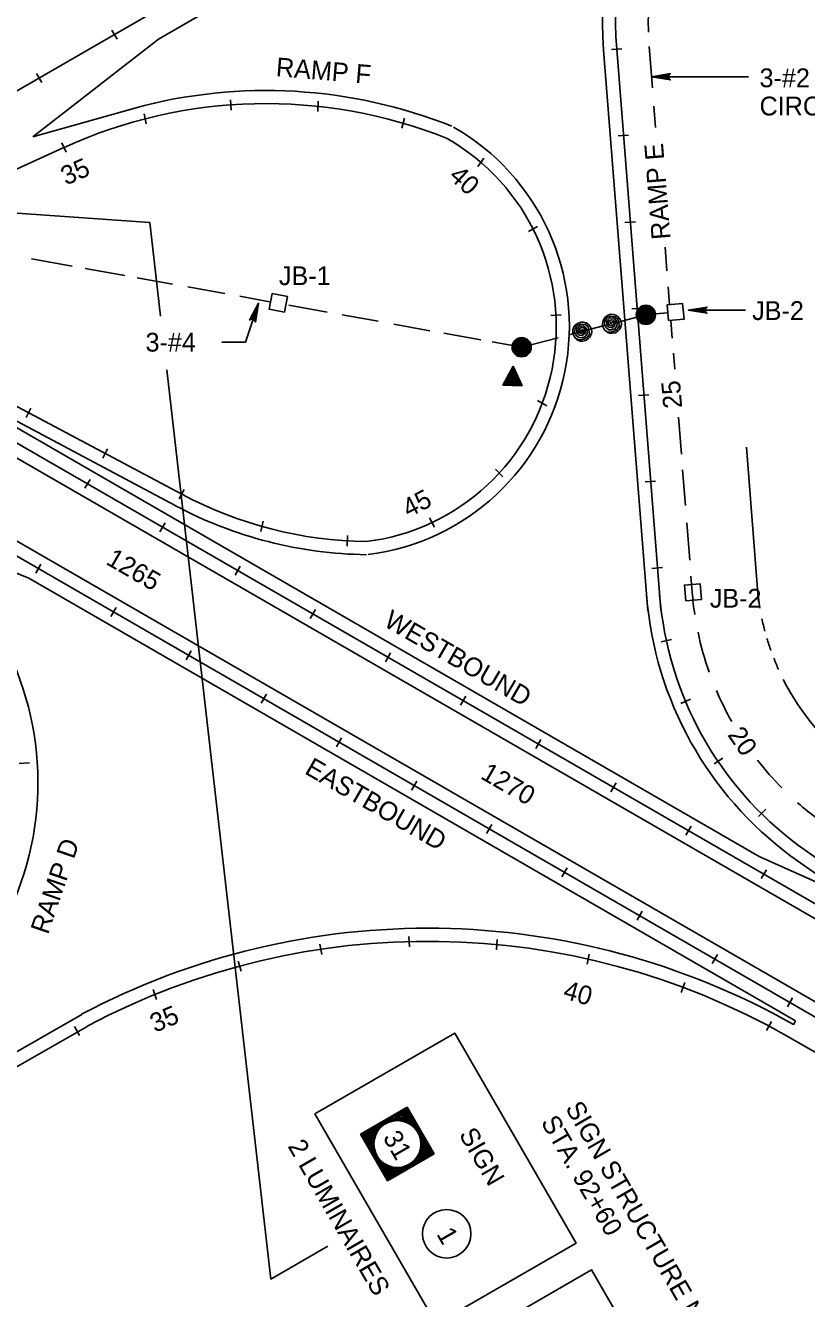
# Model space of a CAD drawing. Extents: x 36 to 2622, y -5330 to 219.
# Drawn here: x 469.4 to 593.7, y -5134.2 to -4931.5 of the extents above; entities that cross this region are included whole.
import ezdxf

# ---------------------------------------------------------------- set-up
doc = ezdxf.new("R2010")
doc.units = 0
doc.layers.add('2', color=7, linetype='Continuous')
doc.layers.add('3', color=7, linetype='Continuous')

# ---------------------------------------------------------------- blocks, each defined once
blk = doc.blocks.new('RARROW')
at = {"layer": '3'}
blk.add_lwpolyline([(-2.2695, 0.285), (-2.184875, 0.12075), (0, 0), (-2.2695, 0.285), (-2.38575, 0.384625), (0, 0), (-2.183125, -0.108), (-2.262875, -0.2705), (0, 0), (-2.38575, -0.379125), (-2.262875, -0.2705)], dxfattribs=at)

msp = doc.modelspace()

# ---------------------------------------------------------------- linework, layer by layer
at = {"layer": '2'}
for p, q in [((569.35, -4888.23), (490.57, -4933.71)), ((280.19, -5050.39), (555.32, -4891.55)), ((483.96, -4933.71), (483.13, -4932.27)), ((490.57, -4933.71), (470.58, -4949.25)), ((568.45, -5024.74), (561.42, -4935.47)), ((562.67, -4935.37), (564.33, -4935.24)), ((563.5, -4935.31), (570.52, -5024.58)), ((568.68, -4934.9), (569.2, -4941.45)), ((472, -4940.61), (471.17, -4939.18)), ((584.5, -4939.7), (569.06, -4939.7)), ((502.01, -4943.36), (502.12, -4945.02)), ((516, -4943.6), (515.95, -4945.26)), ((486.78, -4944.7), (470.58, -4949.25)), ((488.26, -4945.6), (488.6, -4947.22)), ((569.7, -4947.8), (569.43, -4944.37)), ((529.71, -4946.32), (529.29, -4947.92)), ((563.75, -4949.14), (565.4, -4949.02)), ((475.52, -4950.97), (441.69, -4966.41)), ((475.87, -4951.73), (475.18, -4950.22)), ((542.36, -4952.66), (541.39, -4954.01)), ((489.19, -4962.94), (465.78, -4961.29)), ((490.89, -4977.83), (489.19, -4962.94)), ((550.92, -4963.57), (549.45, -4964.35)), ((564.82, -4962.92), (566.47, -4962.79)), ((571.2, -4966.87), (571.5, -4970.62)), ((476.84, -4969.86), (470.33, -4968.69)), ((485.23, -4971.37), (478.87, -4970.23)), ((492.79, -4972.74), (487.19, -4971.73)), ((494.27, -5006.17), (433.76, -4974)), ((501.14, -4974.24), (495.26, -4973.18)), ((571.92, -4976.01), (571.7, -4973.16)), ((508.24, -4975.53), (503.5, -4974.67)), ((504.42, -4981.97), (506.49, -4975.77)), ((517.39, -4977.18), (511.33, -4976.09)), ((699.62, -5134.16), (428.19, -4977.45)), ((525.54, -4978.65), (519.8, -4977.61)), ((554.65, -4977.6), (553, -4977.72)), ((568.15, -4977.62), (563.3, -4978.89)), ((565.89, -4976.68), (567.55, -4976.56)), ((571.62, -4977.29), (568.3, -4977.58)), ((583.99, -4976.87), (574.9, -4976.87)), ((700.67, -5132.35), (434.98, -4978.96)), ((533.78, -4980.14), (528.02, -4979.1)), ((561.55, -4979.34), (556.11, -4980.76)), ((572.12, -4978.5), (572.34, -4981.35)), ((500.62, -4981.97), (504.42, -4981.97)), ((541.87, -4981.6), (536, -4980.54)), ((548.38, -4982.77), (543.69, -4981.92)), ((548.38, -4982.77), (554.16, -4981.27)), ((693.9, -5144.07), (416.96, -4984.17)), ((572.73, -4986.29), (572.53, -4983.7)), ((692.86, -5145.87), (414.78, -4985.32)), ((508.44, -5131.18), (491.87, -4986.4)), ((545.38, -4988.82), (547, -4985.8)), ((545.57, -4988.72), (546.99, -4986.04)), ((545.74, -4988.61), (546.98, -4986.29)), ((546.98, -4986.29), (548.1, -4988.67)), ((546.99, -4986.04), (548.27, -4988.79)), ((547, -4985.8), (548.45, -4988.91)), ((545.93, -4988.51), (546.98, -4986.53)), ((546.1, -4988.4), (546.97, -4986.78)), ((547.75, -4988.45), (546.1, -4988.4)), ((546.28, -4988.3), (546.97, -4987.02)), ((547.58, -4988.33), (546.28, -4988.3)), ((546.46, -4988.19), (546.96, -4987.26)), ((547.41, -4988.22), (546.46, -4988.19)), ((546.64, -4988.09), (546.95, -4987.51)), ((547.23, -4988.11), (546.64, -4988.09)), ((546.82, -4987.98), (546.95, -4987.75)), ((547.06, -4987.99), (546.82, -4987.98)), ((546.95, -4987.51), (547.23, -4988.11)), ((546.95, -4987.75), (547.06, -4987.99)), ((546.96, -4987.26), (547.41, -4988.22)), ((546.97, -4986.78), (547.75, -4988.45)), ((546.97, -4987.02), (547.58, -4988.33)), ((546.98, -4986.53), (547.93, -4988.56)), ((493.3, -5008.01), (459.78, -4990.19)), ((548.45, -4988.91), (545.38, -4988.82)), ((548.27, -4988.79), (545.57, -4988.72)), ((548.1, -4988.67), (545.74, -4988.61)), ((547.93, -4988.56), (545.93, -4988.51)), ((566.97, -4990.46), (568.62, -4990.33)), ((459.5, -4990.71), (586.16, -5063.84)), ((552.39, -4992.08), (550.92, -4991.28)), ((470.26, -4992.49), (469.48, -4993.95)), ((573.33, -4993.92), (573.79, -4999.79)), ((482.46, -4998.97), (481.68, -5000.43)), ((584.14, -4998.71), (586.08, -5023.36)), ((545.36, -5003.42), (544.23, -5002.21)), ((573.99, -5002.29), (574.44, -5007.98)), ((478.84, -5005.24), (479.67, -5003.81)), ((568.04, -5004.22), (569.69, -5004.1)), ((494.66, -5005.45), (493.88, -5006.91)), ((490.8, -5012.15), (491.63, -5010.71)), ((506.84, -5012.1), (507.24, -5010.49)), ((534.52, -5011.4), (533.71, -5009.96)), ((469.91, -5019.56), (448.44, -5010.82)), ((574.65, -5010.76), (575.12, -5016.66)), ((520.6, -5014.43), (520.65, -5012.77)), ((471.03, -5018.76), (471.86, -5017.32)), ((502.76, -5019.05), (503.59, -5017.62)), ((569.11, -5018), (570.77, -5017.87)), ((591.94, -5090.01), (469.91, -5019.56)), ((575.52, -5021.8), (575.32, -5019.21)), ((483, -5025.66), (483.82, -5024.23)), ((514.73, -5025.96), (515.55, -5024.52)), ((572.22, -5029.3), (570.6, -5029.66)), ((494.96, -5032.57), (495.78, -5031.13)), ((526.69, -5032.86), (527.51, -5031.43)), ((506.92, -5039.47), (507.74, -5038.04)), ((538.65, -5039.77), (539.48, -5038.34)), ((575.23, -5038.83), (573.7, -5039.48)), ((518.88, -5046.38), (519.71, -5044.95)), ((550.61, -5046.68), (551.44, -5045.24)), ((470.02, -5048.93), (468.36, -5049.05)), ((580.41, -5048.22), (579.02, -5049.13)), ((530.84, -5053.29), (531.67, -5051.85)), ((562.57, -5053.58), (563.4, -5052.15)), ((587.26, -5056.33), (586.07, -5057.5)), ((542.8, -5060.19), (543.63, -5058.76)), ((574.53, -5060.49), (575.36, -5059.05)), ((615.25, -5078.24), (592.45, -5062.1)), ((586.16, -5063.84), (598.26, -5069.26)), ((598.41, -5068.88), (591.24, -5063.8)), ((554.77, -5067.09), (555.6, -5065.65)), ((586.49, -5067.39), (587.32, -5065.96)), ((566.74, -5073.98), (567.56, -5072.55)), ((530.5, -5078.23), (530.41, -5076.58)), ((544.35, -5078.71), (544.47, -5077.06)), ((516.54, -5079.45), (516.25, -5077.81)), ((558.78, -5081.01), (559.12, -5079.39)), ((578.7, -5080.88), (579.53, -5079.45)), ((503.72, -5082.11), (503.25, -5080.52)), ((489.72, -5085.05), (490.27, -5086.62)), ((573.78, -5085.49), (574.35, -5083.93)), ((590.67, -5087.78), (591.5, -5086.34)), ((450.88, -5104.69), (478.36, -5089.04)), ((451.91, -5106.49), (479.33, -5090.88)), ((477.17, -5090.94), (478, -5092.38)), ((587.35, -5091.59), (588.12, -5090.12)), ((591.66, -5090.64), (591.94, -5090.01)), ((690.43, -5150.08), (590.63, -5092.45)), ((517.54, -5125.93), (508.44, -5131.18))]:
    msp.add_line(p, q, dxfattribs=at)
for points in [[(510.63, -4977.17), (511.1, -4974.71), (508.66, -4974.24), (508.17, -4976.69)], [(571.73, -4978.54), (574.22, -4978.32), (574, -4975.83), (571.51, -4976.05)], [(574.51, -5023.14), (576.99, -5022.92), (576.78, -5020.43), (574.29, -5020.65)], [(515.43, -5104.85), (534.74, -5138.29), (557.03, -5125.42), (537.72, -5091.98)], [(537.2, -5142.56), (556.51, -5176.01), (578.8, -5163.13), (559.5, -5129.69)]]:
    msp.add_lwpolyline(points, close=True, dxfattribs=at)
for points in [[(562.75, -4979.05), (562.47, -4978.99), (562.49, -4978.8), (562.77, -4978.73), (562.98, -4978.87), (562.95, -4979.2), (562.66, -4979.37), (562.32, -4979.24), (562.14, -4978.93), (562.26, -4978.59), (562.65, -4978.42), (563.01, -4978.47), (563.24, -4978.85), (563.23, -4979.3), (562.76, -4979.67), (562.25, -4979.59), (561.91, -4979.2), (561.91, -4978.55), (562.36, -4978.17), (562.97, -4978.12), (563.35, -4978.43), (563.55, -4978.95), (563.54, -4979.41), (563.22, -4979.85), (562.74, -4980.01), (562.23, -4979.98), (561.81, -4979.64), (561.54, -4979.1), (561.61, -4978.65), (561.92, -4978.1), (562.51, -4977.84), (563.25, -4977.91), (563.68, -4978.29), (563.82, -4978.8), (563.9, -4979.43), (563.58, -4979.94), (563, -4980.26), (562.43, -4980.38), (562, -4980.33), (561.61, -4980.05), (561.35, -4979.61), (561.25, -4979.17), (561.27, -4978.73), (561.43, -4978.29), (561.73, -4977.92), (562.14, -4977.67), (562.58, -4977.53), (562.98, -4977.55), (563.38, -4977.66), (563.73, -4977.91), (564.02, -4978.25), (564.21, -4978.66), (564.26, -4979.16), (564.18, -4979.52), (563.98, -4979.92), (563.68, -4980.22), (563.26, -4980.47), (562.8, -4980.56), (562.43, -4980.54), (562.07, -4980.42), (561.8, -4980.23)], [(558.01, -4980.29), (557.73, -4980.24), (557.75, -4980.04), (558.03, -4979.98), (558.24, -4980.12), (558.21, -4980.45), (557.91, -4980.61), (557.58, -4980.49), (557.4, -4980.17), (557.52, -4979.84), (557.91, -4979.66), (558.27, -4979.71), (558.5, -4980.09), (558.49, -4980.54), (558.02, -4980.91), (557.51, -4980.83), (557.17, -4980.44), (557.17, -4979.79), (557.62, -4979.41), (558.23, -4979.36), (558.61, -4979.67), (558.81, -4980.19), (558.8, -4980.65), (558.48, -4981.09), (558, -4981.26), (557.49, -4981.23), (557.07, -4980.89), (556.8, -4980.35), (556.87, -4979.9), (557.18, -4979.34), (557.77, -4979.09), (558.51, -4979.15), (558.94, -4979.54), (559.08, -4980.04), (559.15, -4980.68), (558.84, -4981.19), (558.26, -4981.5), (557.69, -4981.62), (557.26, -4981.57), (556.87, -4981.3), (556.61, -4980.85), (556.5, -4980.42), (556.53, -4979.98), (556.69, -4979.54), (556.99, -4979.17), (557.39, -4978.92), (557.84, -4978.77), (558.24, -4978.8), (558.64, -4978.91), (558.99, -4979.15), (559.27, -4979.49), (559.47, -4979.91), (559.52, -4980.4), (559.44, -4980.76), (559.24, -4981.16), (558.94, -4981.46), (558.52, -4981.72), (558.06, -4981.8), (557.69, -4981.79), (557.33, -4981.67), (557.06, -4981.47)], [(522.74, -5108.07), (530.17, -5103.78)], [(534.46, -5111.21), (530.17, -5103.78)], [(527.03, -5115.5), (522.74, -5108.07)], [(527.03, -5115.5), (534.46, -5111.21)]]:
    msp.add_lwpolyline(points, dxfattribs=at)
for centre, radius in [((568.15, -4977.62), 1.53), ((568.15, -4977.62), 1.42), ((568.15, -4977.62), 1.31), ((568.15, -4977.62), 1.21), ((568.15, -4977.62), 1.1), ((568.15, -4977.62), 0.988), ((568.15, -4977.62), 0.879), ((568.15, -4977.62), 0.77), ((568.15, -4977.62), 0.662), ((568.15, -4977.62), 0.553), ((568.15, -4977.62), 0.444), ((568.15, -4977.62), 0.335), ((568.15, -4977.62), 0.226), ((568.15, -4977.62), 0.118), ((548.38, -4982.77), 1.53), ((548.38, -4982.77), 1.42), ((548.38, -4982.77), 1.31), ((548.38, -4982.77), 1.21), ((548.38, -4982.77), 1.1), ((548.38, -4982.77), 0.988), ((548.38, -4982.77), 0.879), ((548.38, -4982.77), 0.77), ((548.38, -4982.77), 0.662), ((548.38, -4982.77), 0.553), ((548.38, -4982.77), 0.444), ((548.38, -4982.77), 0.335), ((548.38, -4982.77), 0.226), ((548.38, -4982.77), 0.118), ((528.6, -5109.64), 4.12), ((528.6, -5109.64), 3.95), ((528.6, -5109.64), 3.74), ((536.44, -5123.93), 3.86)]:
    msp.add_circle(centre, radius, dxfattribs=at)
for centre, radius, start, end in [((617.25, -4931.08), 56, 117.5941, 184.4997), ((617.25, -4931.08), 53.92, 117.5941, 184.4997), ((617.25, -4931.08), 48.72, 175.9458, 181.7858), ((507.69, -5021.49), 79.59, 68.1807, 105.2322), ((507.69, -5021.49), 77.51, 68.1807, 114.519), ((519.38, -4979.49), 36.58, 277.1666, 60.2478), ((519.38, -4979.49), 34.5, 277.1666, 60.2478), ((524.54, -4949.24), 64.49, 242.0007, 269.2348), ((524.54, -4949.24), 66.57, 242.0007, 269.2348), ((422.96, -5052.11), 48.42, 302.5087, 54.6076), ((625.35, -5017.8), 57.27, 184.5916, 233.4476), ((625.35, -5017.8), 55.19, 184.5916, 233.3995), ((625.35, -5017.8), 49.99, 184.5916, 188.6652), ((625.35, -5017.8), 39.59, 184.5928, 189.5111), ((625.35, -5017.8), 39.59, 191.9665, 194.9428), ((625.35, -5017.8), 49.99, 191.9521, 199.5366), ((625.35, -5017.8), 39.59, 196.675, 199.5883), ((625.35, -5017.8), 39.59, 201.4586, 204.2855), ((625.35, -5017.8), 39.59, 206.8227, 233.4003), ((625.35, -5017.8), 49.99, 203.1493, 209.4326), ((625.35, -5017.8), 49.99, 217.9485, 224.6501), ((625.35, -5017.8), 49.99, 228.5971, 233.3995), ((533.47, -5193.22), 117.94, 60.4381, 117.8815), ((533.47, -5193.22), 115.86, 60.4381, 117.8802), ((528.6, -5109.64), 4.32, 36.379, 113.621), ((528.6, -5109.64), 4.53, 48.594, 101.406), ((528.6, -5109.64), 4.73, 54.8374, 95.1626), ((528.6, -5109.64), 4.88, 58.4912, 91.5088), ((528.6, -5109.64), 5.06, 62.0046, 87.9954), ((528.6, -5109.64), 5.26, 65.2513, 84.7486), ((528.6, -5109.64), 5.44, 67.9632, 82.0368), ((528.6, -5109.64), 5.62, 70.1586, 79.8414), ((528.6, -5109.64), 5.8, 72.2128, 77.7872), ((528.6, -5109.64), 5.8, 162.2128, 167.7199), ((528.6, -5109.64), 5.62, 160.1586, 169.769), ((528.6, -5109.64), 5.44, 157.9632, 171.9586), ((528.6, -5109.64), 5.26, 155.2513, 174.6623), ((528.6, -5109.64), 5.06, 152.0046, 177.8978), ((528.6, -5109.64), 4.88, 148.4912, 181.3964), ((528.6, -5109.64), 4.73, 144.8374, 185.031), ((528.6, -5109.64), 4.53, 138.594, 191.2253), ((528.6, -5109.64), 4.32, 126.379, 203.0962), ((528.6, -5109.64), 4.32, 306.9038, 23.621), ((528.6, -5109.64), 4.53, 318.7747, 11.406), ((528.6, -5109.64), 4.73, 324.969, 5.1626), ((528.6, -5109.64), 4.88, 328.6036, 1.5088), ((528.6, -5109.64), 5.06, 332.1022, 357.9954), ((528.6, -5109.64), 5.26, 335.3377, 354.7486), ((528.6, -5109.64), 5.44, 338.0414, 352.0368), ((528.6, -5109.64), 5.62, 340.231, 349.8414), ((528.6, -5109.64), 5.8, 342.2801, 347.7872), ((528.6, -5109.64), 4.32, 216.9038, 293.0962), ((528.6, -5109.64), 4.53, 228.7747, 281.2253), ((528.6, -5109.64), 4.73, 234.969, 275.031), ((528.6, -5109.64), 4.88, 238.6036, 271.3964), ((528.6, -5109.64), 5.06, 242.1022, 267.8978), ((528.6, -5109.64), 5.26, 245.3377, 264.6623), ((528.6, -5109.64), 5.44, 248.0414, 261.9586), ((528.6, -5109.64), 5.62, 250.231, 259.769), ((528.6, -5109.64), 5.8, 252.2801, 257.7199)]:
    msp.add_arc(centre, radius, start, end, dxfattribs=at)

# ---------------------------------------------------------------- block references
at = {"layer": '2', "xscale": 1.2574347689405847, "yscale": 1.3092961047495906}
for p, rotation in [((569.06, -4939.7), 180), ((506.49, -4975.77), 71.42776193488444), ((574.9, -4976.87), 180)]:
    msp.add_blockref('RARROW', p, dxfattribs=dict(at, rotation=rotation))

# ---------------------------------------------------------------- texts
at = {"layer": '2'}
for s, height, rotation, p in [('RAMP F', 2.996, 355.2917, (509.18, -4939.61)), ('3-#2', 2.995, 360, (586.24, -4941.38)), ('CIRCUIT B', 2.995, 360, (586.24, -4945.87)), ('RAMP E', 2.996, 94.4995, (572.07, -4965.52)), ('35', 2.996, 23.5207, (475.83, -4957.05)), ('40', 2.996, 317.3246, (536.63, -4955.76)), ('3-#4', 2.996, 360, (488.5, -4983.47)), ('25', 2.996, 95.0793, (573.94, -4992.4)), ('45', 2.996, 27.5003, (530.38, -5009.97)), ('1265', 2.996, 330, (482.03, -5017.22)), ('WESTBOUND', 2.996, 330.0015, (526.23, -5027.07)), ('20', 2.996, 304.8235, (581.05, -5044.5)), ('EASTBOUND', 2.996, 330.0015, (513.66, -5050.57)), ('1270', 2.996, 330, (541.66, -5051.35)), ('RAMP D', 2.996, 71.0637, (472.96, -5076.4)), ('40', 2.996, 343.95, (554.81, -5086.42)), ('35', 2.996, 22.964, (490, -5091.95)), ('SIGN STRUCTURE NO.7', 2.9955, 300, (555.25, -5103.91)), ('STA. 92+60', 2.996, 300, (551.36, -5106.16)), ('31', 2.995, 300, (526.21, -5108.59)), ('SIGN', 2.995, 300, (538.32, -5108.11)), ('2 LUMINAIRES', 2.9955, 300, (511.07, -5109.98)), ('1', 3, 300, (534.74, -5123.97))]:
    msp.add_text(s, height=height, rotation=rotation, dxfattribs=at).set_placement(p)
for s, p in [('JB-1', (509.73, -4972.89)), ('JB-2', (585.06, -4978.44)), ('JB-2', (578.32, -5024.24))]:
    msp.add_text(s, height=2.996, dxfattribs=at).set_placement(p)

doc.saveas('drawing.dxf')
